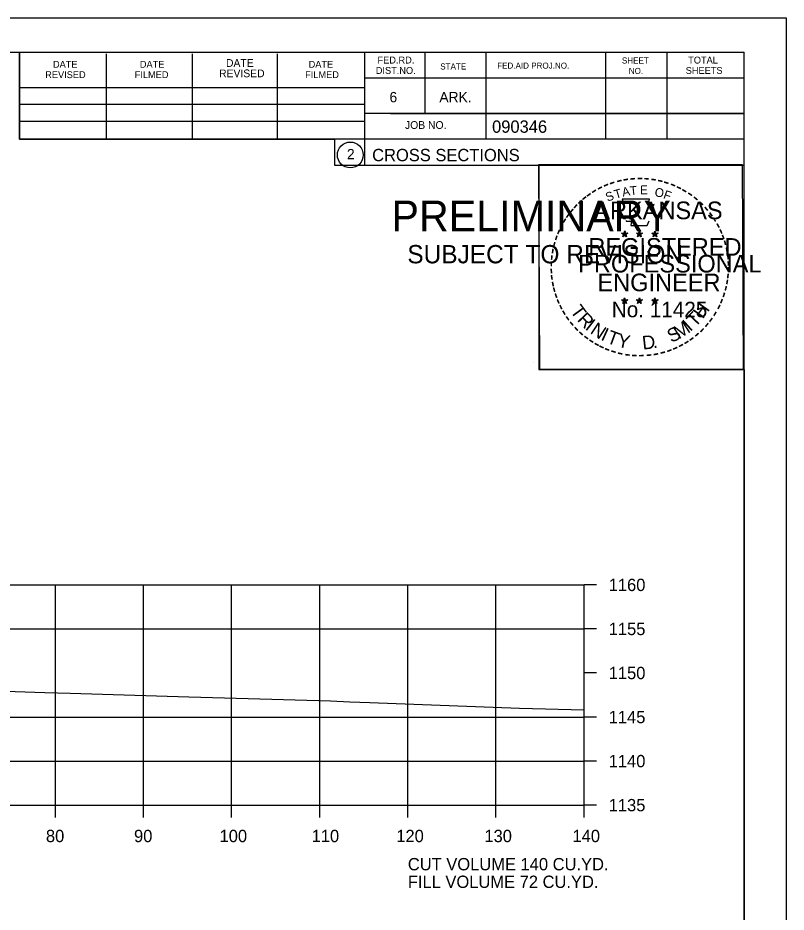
# Model space of a CAD drawing. Extents: x 1368971 to 1374497, y 378717 to 381839.
# Drawn here: x 1372484.6 to 1372571.8, y 381441.8 to 381543.3 of the extents above; entities that cross this region are included whole.
import ezdxf

# ---------------------------------------------------------------- set-up
doc = ezdxf.new("R2010")
doc.units = 0
for name, color, linetype in [('R_Axis', 7, 'Continuous'), ('R_Axis Annot', 7, 'Continuous'), ('R_Border', 7, 'Continuous'), ('R_Border PE', 7, 'Continuous'), ('R_Border Prem', 7, 'Continuous'), ('R_Exist Surface', 7, 'Continuous'), ('R_Grid', 7, 'Continuous'), ('R_No Plot', 7, 'Continuous')]:
    doc.layers.add(name, color=color, linetype=linetype)

msp = doc.modelspace()

# ---------------------------------------------------------------- linework, layer by layer
at = {"layer": 'R_Axis'}
for p, q in [((1372548.91, 381453.99), (1372548.91, 381478.99)), ((1372550.31, 381478.99), (1372548.91, 381478.99)), ((1372550.31, 381473.99), (1372548.91, 381473.99)), ((1372550.31, 381468.99), (1372548.91, 381468.99)), ((1372550.31, 381463.99), (1372548.91, 381463.99)), ((1372550.31, 381458.99), (1372548.91, 381458.99)), ((1372268.91, 381453.99), (1372548.91, 381453.99)), ((1372488.91, 381452.59), (1372488.91, 381453.99)), ((1372498.91, 381452.59), (1372498.91, 381453.99)), ((1372508.91, 381452.59), (1372508.91, 381453.99)), ((1372518.91, 381452.59), (1372518.91, 381453.99)), ((1372528.91, 381452.59), (1372528.91, 381453.99)), ((1372538.91, 381452.59), (1372538.91, 381453.99)), ((1372548.91, 381452.59), (1372548.91, 381453.99)), ((1372550.31, 381453.99), (1372548.91, 381453.99))]:
    msp.add_line(p, q, dxfattribs=at)
at = {"layer": 'R_Border'}
for p, q in [((1372250.91, 381539.45), (1372567.09, 381539.45)), ((1372484.83, 381529.57), (1372484.83, 381539.45)), ((1372494.69, 381529.57), (1372494.69, 381539.25)), ((1372504.45, 381529.57), (1372504.45, 381539.25)), ((1372514.13, 381529.57), (1372514.13, 381539.25)), ((1372523.99, 381539.45), (1372523.99, 381526.65)), ((1372530.83, 381539.45), (1372530.83, 381532.51)), ((1372537.77, 381539.45), (1372537.77, 381529.57)), ((1372551.35, 381539.45), (1372551.35, 381529.57)), ((1372558.29, 381539.45), (1372558.29, 381529.57)), ((1372567.09, 381333.99), (1372567.09, 381539.45)), ((1372567.09, 381536.51), (1372523.99, 381536.51)), ((1372567.09, 381536.53), (1372567.09, 381536.53)), ((1372484.83, 381535.43), (1372523.99, 381535.43)), ((1372484.83, 381533.57), (1372523.99, 381533.57)), ((1372567.09, 381532.51), (1372523.99, 381532.51)), ((1372526.95, 381532.51), (1372567.09, 381532.51)), ((1372484.83, 381529.57), (1372484.83, 381531.63)), ((1372484.83, 381531.63), (1372523.99, 381531.63)), ((1372567.09, 381529.57), (1372484.83, 381529.57)), ((1372523.99, 381526.65), (1372567.09, 381526.65))]:
    msp.add_line(p, q, dxfattribs=at)
msp.add_circle((1372522.38, 381527.79), 1.47, dxfattribs=at)
at = {"layer": 'R_Border PE'}
for p, q in [((1372553.18, 381518.91), (1372553.53, 381518.8)), ((1372553.18, 381518.91), (1372553.43, 381518.86)), ((1372553.18, 381518.91), (1372553.42, 381518.79)), ((1372553.31, 381518.5), (1372553.53, 381518.8)), ((1372553.53, 381519.16), (1372553.49, 381518.91)), ((1372553.53, 381518.8), (1372553.53, 381519.16)), ((1372553.53, 381519.16), (1372553.58, 381518.91)), ((1372553.88, 381518.91), (1372553.53, 381518.8)), ((1372553.74, 381518.5), (1372553.53, 381518.8)), ((1372553.88, 381518.91), (1372553.59, 381518.86)), ((1372553.74, 381518.5), (1372553.6, 381518.79)), ((1372553.88, 381518.91), (1372553.67, 381518.81)), ((1372554.85, 381518.91), (1372555.2, 381518.8)), ((1372554.85, 381518.91), (1372555.1, 381518.86)), ((1372554.85, 381518.91), (1372555.09, 381518.79)), ((1372554.98, 381518.5), (1372555.2, 381518.8)), ((1372555.2, 381519.16), (1372555.16, 381518.91)), ((1372555.2, 381518.8), (1372555.2, 381519.16)), ((1372555.2, 381519.16), (1372555.25, 381518.91)), ((1372555.55, 381518.91), (1372555.2, 381518.8)), ((1372555.41, 381518.5), (1372555.2, 381518.8)), ((1372555.55, 381518.91), (1372555.26, 381518.86)), ((1372555.41, 381518.5), (1372555.27, 381518.79)), ((1372555.55, 381518.91), (1372555.34, 381518.81)), ((1372556.61, 381518.9), (1372556.96, 381518.79)), ((1372556.61, 381518.9), (1372556.87, 381518.85)), ((1372556.61, 381518.9), (1372556.85, 381518.78)), ((1372556.75, 381518.49), (1372556.96, 381518.79)), ((1372556.96, 381519.15), (1372556.92, 381518.9)), ((1372556.96, 381518.79), (1372556.96, 381519.15)), ((1372556.96, 381519.15), (1372557.01, 381518.9)), ((1372557.31, 381518.9), (1372556.96, 381518.79)), ((1372557.18, 381518.49), (1372556.96, 381518.79)), ((1372557.31, 381518.9), (1372557.02, 381518.85)), ((1372557.18, 381518.49), (1372557.04, 381518.78)), ((1372557.31, 381518.9), (1372557.11, 381518.8)), ((1372553.31, 381518.5), (1372553.44, 381518.75)), ((1372553.31, 381518.5), (1372553.53, 381518.72)), ((1372553.74, 381518.5), (1372553.53, 381518.72)), ((1372554.98, 381518.5), (1372555.11, 381518.75)), ((1372554.98, 381518.5), (1372555.2, 381518.72)), ((1372555.41, 381518.5), (1372555.2, 381518.72)), ((1372556.75, 381518.49), (1372556.87, 381518.73)), ((1372556.75, 381518.49), (1372556.96, 381518.71)), ((1372557.18, 381518.49), (1372556.96, 381518.7)), ((1372553.18, 381511.34), (1372553.52, 381511.23)), ((1372553.18, 381511.34), (1372553.43, 381511.29)), ((1372553.18, 381511.34), (1372553.41, 381511.21)), ((1372553.31, 381510.93), (1372553.52, 381511.23)), ((1372553.31, 381510.93), (1372553.43, 381511.17)), ((1372553.31, 381510.93), (1372553.52, 381511.15)), ((1372553.52, 381511.59), (1372553.48, 381511.34)), ((1372553.52, 381511.23), (1372553.52, 381511.59)), ((1372553.52, 381511.59), (1372553.57, 381511.34)), ((1372553.87, 381511.34), (1372553.52, 381511.23)), ((1372553.74, 381510.93), (1372553.52, 381511.23)), ((1372553.74, 381510.93), (1372553.52, 381511.14)), ((1372553.87, 381511.34), (1372553.59, 381511.29)), ((1372553.74, 381510.93), (1372553.6, 381511.22)), ((1372553.87, 381511.34), (1372553.67, 381511.23)), ((1372554.84, 381511.34), (1372555.19, 381511.23)), ((1372554.84, 381511.34), (1372555.1, 381511.29)), ((1372554.84, 381511.34), (1372555.08, 381511.21)), ((1372554.98, 381510.93), (1372555.19, 381511.23)), ((1372554.98, 381510.93), (1372555.1, 381511.17)), ((1372554.98, 381510.93), (1372555.19, 381511.15)), ((1372555.19, 381511.59), (1372555.15, 381511.34)), ((1372555.19, 381511.23), (1372555.19, 381511.59)), ((1372555.19, 381511.59), (1372555.24, 381511.34)), ((1372555.54, 381511.34), (1372555.19, 381511.23)), ((1372555.41, 381510.93), (1372555.19, 381511.23)), ((1372555.41, 381510.93), (1372555.19, 381511.14)), ((1372555.54, 381511.34), (1372555.25, 381511.29)), ((1372555.41, 381510.93), (1372555.27, 381511.22)), ((1372555.54, 381511.34), (1372555.34, 381511.23)), ((1372556.61, 381511.33), (1372556.96, 381511.22)), ((1372556.61, 381511.33), (1372556.86, 381511.28)), ((1372556.61, 381511.33), (1372556.85, 381511.2)), ((1372556.74, 381510.92), (1372556.96, 381511.22)), ((1372556.74, 381510.92), (1372556.87, 381511.16)), ((1372556.74, 381510.92), (1372556.96, 381511.14)), ((1372556.96, 381511.58), (1372556.92, 381511.33)), ((1372556.96, 381511.22), (1372556.96, 381511.58)), ((1372556.96, 381511.58), (1372557.01, 381511.33)), ((1372557.31, 381511.33), (1372556.96, 381511.22)), ((1372557.17, 381510.92), (1372556.96, 381511.22)), ((1372557.17, 381510.92), (1372556.96, 381511.13)), ((1372557.31, 381511.33), (1372557.02, 381511.28)), ((1372557.17, 381510.92), (1372557.04, 381511.21)), ((1372557.31, 381511.33), (1372557.1, 381511.22))]:
    msp.add_line(p, q, dxfattribs=at)
for points in [[(1372553.22, 381522.79), (1372553.49, 381521.96)], [(1372556.73, 381521.87), (1372556.87, 381522.15), (1372556.19, 381522.13), (1372556.34, 381522.79), (1372553.22, 381522.79)], [(1372553.71, 381520.36), (1372553.71, 381520.28), (1372554.28, 381520.26), (1372554.22, 381519.79), (1372556.09, 381519.79), (1372556.29, 381520.32)], [(1372553.53, 381519.16), (1372553.74, 381518.5), (1372553.18, 381518.91), (1372553.88, 381518.91), (1372553.31, 381518.5), (1372553.53, 381519.16)], [(1372555.2, 381519.16), (1372555.41, 381518.5), (1372554.85, 381518.91), (1372555.55, 381518.91), (1372554.98, 381518.5), (1372555.2, 381519.16)], [(1372556.96, 381519.15), (1372557.18, 381518.49), (1372556.61, 381518.9), (1372557.31, 381518.9), (1372556.75, 381518.49), (1372556.96, 381519.15)], [(1372553.52, 381511.59), (1372553.74, 381510.93), (1372553.18, 381511.34), (1372553.87, 381511.34), (1372553.31, 381510.93), (1372553.52, 381511.59)], [(1372555.19, 381511.59), (1372555.41, 381510.93), (1372554.84, 381511.34), (1372555.54, 381511.34), (1372554.98, 381510.93), (1372555.19, 381511.59)], [(1372556.96, 381511.58), (1372557.17, 381510.92), (1372556.61, 381511.33), (1372557.31, 381511.33), (1372556.74, 381510.92), (1372556.96, 381511.58)]]:
    msp.add_lwpolyline(points, dxfattribs=at)
for centre, radius in [((1372553.53, 381518.8), 0.172), ((1372553.53, 381518.8), 0.145), ((1372553.53, 381518.8), 0.116), ((1372553.53, 381518.8), 0.0991), ((1372553.53, 381518.8), 0.0747), ((1372553.53, 381518.8), 0.0495), ((1372553.53, 381518.8), 0.0296), ((1372555.2, 381518.8), 0.172), ((1372555.2, 381518.8), 0.145), ((1372555.2, 381518.8), 0.116), ((1372555.2, 381518.8), 0.0991), ((1372555.2, 381518.8), 0.0747), ((1372555.2, 381518.8), 0.0495), ((1372555.2, 381518.8), 0.0296), ((1372556.96, 381518.79), 0.172), ((1372556.96, 381518.79), 0.145), ((1372556.96, 381518.79), 0.116), ((1372556.96, 381518.79), 0.0991), ((1372556.96, 381518.79), 0.0747), ((1372556.96, 381518.79), 0.0495), ((1372556.96, 381518.79), 0.0296), ((1372553.52, 381511.22), 0.172), ((1372553.52, 381511.22), 0.145), ((1372553.52, 381511.22), 0.116), ((1372553.52, 381511.22), 0.0991), ((1372553.52, 381511.22), 0.0747), ((1372553.52, 381511.22), 0.0495), ((1372553.52, 381511.22), 0.0296), ((1372555.19, 381511.22), 0.172), ((1372555.19, 381511.22), 0.145), ((1372555.19, 381511.22), 0.116), ((1372555.19, 381511.22), 0.0991), ((1372555.19, 381511.22), 0.0747), ((1372555.19, 381511.22), 0.0495), ((1372555.19, 381511.22), 0.0296), ((1372556.96, 381511.21), 0.172), ((1372556.96, 381511.21), 0.145), ((1372556.96, 381511.21), 0.116), ((1372556.96, 381511.21), 0.0991), ((1372556.96, 381511.21), 0.0747), ((1372556.96, 381511.21), 0.0495), ((1372556.96, 381511.21), 0.0296)]:
    msp.add_circle(centre, radius, dxfattribs=at)
at = {"layer": 'R_Exist Surface'}
msp.add_lwpolyline([(1372475.29, 381467.2), (1372487.72, 381466.78), (1372490.6, 381466.69), (1372504.05, 381466.29), (1372510.77, 381466.09), (1372520.15, 381465.82), (1372522.34, 381465.72), (1372524.61, 381465.64), (1372541.58, 381465.01), (1372548.91, 381464.79)], dxfattribs=at)
at = {"layer": 'R_Grid'}
for p, q in [((1372268.91, 381478.99), (1372548.91, 381478.99)), ((1372488.91, 381453.99), (1372488.91, 381478.99)), ((1372498.91, 381453.99), (1372498.91, 381478.99)), ((1372508.91, 381453.99), (1372508.91, 381478.99)), ((1372518.91, 381453.99), (1372518.91, 381478.99)), ((1372528.91, 381453.99), (1372528.91, 381478.99)), ((1372538.91, 381453.99), (1372538.91, 381478.99)), ((1372548.91, 381453.99), (1372548.91, 381478.99)), ((1372268.91, 381473.99), (1372548.91, 381473.99)), ((1372268.91, 381463.99), (1372548.91, 381463.99)), ((1372268.91, 381458.99), (1372548.91, 381458.99)), ((1372268.91, 381453.99), (1372548.91, 381453.99))]:
    msp.add_line(p, q, dxfattribs=at)
at = {"layer": 'R_No Plot'}
for p, q in [((1372238.51, 381543.35), (1372571.85, 381543.35)), ((1372543.13, 381504.2), (1372543.13, 381504.2))]:
    msp.add_line(p, q, dxfattribs=at)
for points in [[(1372238.51, 381543.35), (1372571.85, 381543.35), (1372571.85, 381330.01), (1372238.51, 381330.01)], [(1372484.83, 381539.45), (1372484.83, 381529.57), (1372520.57, 381529.57), (1372520.57, 381526.65), (1372543.77, 381526.65), (1372543.77, 381503.44), (1372567.09, 381503.44), (1372567.09, 381333.99), (1372250.91, 381333.99), (1372250.91, 381539.45)], [(1372543.77, 381526.69), (1372566.86, 381526.69), (1372566.98, 381503.44), (1372543.88, 381503.44)]]:
    msp.add_lwpolyline(points, close=True, dxfattribs=at)

# ---------------------------------------------------------------- texts
at = {"layer": 'R_Axis Annot'}
for s, p in [('1160', (1372551.71, 381478.29)), ('1155', (1372551.71, 381473.29)), ('1150', (1372551.71, 381468.29)), ('1145', (1372551.71, 381463.29)), ('1140', (1372551.71, 381458.29)), ('1135', (1372551.71, 381453.29)), ('80', (1372487.83, 381449.79)), ('90', (1372497.83, 381449.79)), ('100', (1372507.54, 381449.79)), ('110', (1372517.99, 381449.79)), ('120', (1372527.6, 381449.79)), ('130', (1372537.6, 381449.79)), ('140', (1372547.6, 381449.79)), ('CUT VOLUME 140 CU.YD.', (1372528.91, 381446.59)), ('FILL VOLUME 72 CU.YD.', (1372528.91, 381444.59))]:
    msp.add_text(s, height=1.4, dxfattribs=at).set_placement(p)
at = {"layer": 'R_Border'}
for s, height, p in [('DATE', 0.782, (1372488.63, 381537.69)), ('DATE', 0.782, (1372498.49, 381537.69)), ('DATE', 0.879, (1372508.27, 381537.79)), ('DATE', 0.782, (1372517.65, 381537.69)), ('FED.RD.', 0.782, (1372525.47, 381538.17)), ('STATE', 0.684, (1372532.59, 381537.49)), ('FED.AID PROJ.NO.', 0.684, (1372539.05, 381537.59)), ('SHEET', 0.684, (1372553.21, 381538.17)), ('TOTAL', 0.782, (1372560.73, 381538.17)), ('REVISED', 0.782, (1372487.75, 381536.51)), ('FILMED', 0.782, (1372497.91, 381536.51)), ('REVISED', 0.879, (1372507.49, 381536.61)), ('FILMED', 0.782, (1372517.25, 381536.51)), ('DIST.NO.', 0.782, (1372525.27, 381536.99)), ('NO.', 0.684, (1372553.99, 381536.99)), ('SHEETS', 0.782, (1372560.45, 381536.99)), ('6', 1.17, (1372526.83, 381533.77)), ('ARK.', 1.172, (1372532.49, 381533.77)), ('JOB NO.', 0.879, (1372528.59, 381530.75)), ('2', 1.17, (1372522, 381527.3)), ('CROSS SECTIONS', 1.4, (1372524.86, 381527.08))]:
    msp.add_text(s, height=height, dxfattribs=at).set_placement(p)
msp.add_text('090346', height=1.4, rotation=360, dxfattribs=at).set_placement((1372538.47, 381530.31))
at = {"layer": 'R_Border PE'}
for s, height, rotation, p in [('-', 1.6, 13.6301, (1372552.72, 381524.16)), ('-', 1.6, 10.2193, (1372553.4, 381524.32)), ('-', 1.6, 5.8968, (1372554.13, 381524.43)), ('-', 1.6, 0.1862, (1372554.9, 381524.5)), ('-', 1.6, 357.743, (1372555.62, 381524.49)), ('-', 1.6, 352.1617, (1372556.36, 381524.43)), ('-', 1.6, 347.2049, (1372557.08, 381524.32)), ('-', 1.6, 34.0636, (1372550.1, 381522.96)), ('-', 1.6, 28.7918, (1372550.7, 381523.33)), ('-', 1.6, 24.3072, (1372551.33, 381523.65)), ('-', 1.6, 19.1761, (1372551.97, 381523.91)), ('T', 1, 16.4036, (1372552.49, 381522.8)), ('A', 1, 11.2132, (1372553.32, 381523.05)), ('T', 1, 6.0228, (1372554.16, 381523.21)), ('E', 1, 0.8323, (1372555.27, 381523.32)), ('O', 1, 350.4515, (1372556.87, 381523.11)), ('-', 1.6, 342.3362, (1372557.72, 381524.16)), ('-', 1.6, 337.8551, (1372558.45, 381523.94)), ('-', 1.6, 334.1211, (1372559.08, 381523.67)), ('-', 1.6, 329.6409, (1372559.66, 381523.38)), ('-', 1.6, 38.9507, (1372549.05, 381522.19)), ('-', 1.6, 36.2317, (1372549.53, 381522.56)), ('S', 1, 21.594, (1372551.58, 381522.47)), ('F', 1, 340.0707, (1372557.83, 381522.89)), ('-', 1.6, 325.8627, (1372560.31, 381523.02)), ('-', 1.6, 320.5297, (1372560.92, 381522.6)), ('-', 1.6, 48.423, (1372548.17, 381521.29)), ('-', 1.6, 42.9622, (1372548.62, 381521.77)), ('-', 1.6, 315.5786, (1372561.52, 381522.11)), ('-', 1.6, 309.8797, (1372562.08, 381521.56)), ('-', 1.6, 54.2325, (1372547.35, 381520.24)), ('-', 1.6, 50.6142, (1372547.77, 381520.8)), ('-', 1.6, 306.6522, (1372562.61, 381520.96)), ('-', 1.6, 62.8713, (1372546.72, 381519.1)), ('-', 1.6, 58.0706, (1372547.03, 381519.71)), ('-', 1.4, 303.6753, (1372563.1, 381520.39)), ('-', 1.6, 299.6684, (1372563.41, 381519.78)), ('-', 1.6, 67.7743, (1372546.46, 381518.49)), ('-', 1.6, 294.6628, (1372563.74, 381519.17)), ('-', 1.6, 290.5728, (1372564, 381518.59)), ('-', 1.6, 75.461, (1372546.04, 381517.14)), ('-', 1.6, 72.3945, (1372546.24, 381517.86)), ('-', 1.6, 285.1233, (1372564.23, 381518.01)), ('-', 1.6, 81.2013, (1372545.91, 381516.43)), ('-', 1.6, 280.5493, (1372564.43, 381517.27)), ('-', 1.6, 85.1863, (1372545.83, 381515.74)), ('-', 1.6, 276.5962, (1372564.59, 381516.5)), ('-', 1.6, 274.3301, (1372564.65, 381515.78)), ('-', 1.6, 94.1959, (1372545.84, 381514.31)), ('-', 1.6, 89.0622, (1372545.81, 381515.04)), ('-', 1.6, 269.9407, (1372564.69, 381515.15)), ('-', 1.6, 98.9479, (1372545.91, 381513.64)), ('-', 1.6, 263.5172, (1372564.67, 381514.48)), ('-', 1.6, 101.7149, (1372546.05, 381512.91)), ('-', 1.6, 105.4578, (1372546.21, 381512.32)), ('-', 1.6, 255.7626, (1372564.49, 381513.15)), ('-', 1.6, 260.9953, (1372564.6, 381513.83)), ('-', 1.6, 109.0874, (1372546.43, 381511.69)), ('-', 1.6, 252.8681, (1372564.3, 381512.43)), ('-', 1.6, 114.0643, (1372546.68, 381511.09)), ('-', 1.6, 115.7288, (1372546.99, 381510.47)), ('T', 1.54, 306.0406, (1372547.28, 381510.06)), ('H', 1.54, 54.6088, (1372562.4, 381509.1)), ('-', 1.6, 244.6197, (1372563.82, 381511.13)), ('-', 1.6, 247.8887, (1372564.08, 381511.76)), ('-', 1.6, 120.4471, (1372547.34, 381509.89)), ('R', 1.54, 314.005, (1372548.05, 381509.02)), ('T', 1.54, 46.6444, (1372561.51, 381508.16)), ('-', 1.6, 239.0712, (1372563.43, 381510.38)), ('-', 1.6, 125.8934, (1372547.75, 381509.32)), ('-', 1.6, 130.7181, (1372548.21, 381508.77)), ('I', 1.54, 321.9694, (1372548.95, 381508.08)), ('N', 1.54, 326.5002, (1372549.51, 381507.61)), ('M', 1.54, 32.6563, (1372559.67, 381506.83)), ('I', 1.54, 42.1136, (1372560.95, 381507.68)), ('-', 1.6, 231.2538, (1372562.59, 381509.16)), ('-', 1.6, 233.8452, (1372563.02, 381509.72)), ('-', 1.6, 134.2238, (1372548.72, 381508.23)), ('-', 1.6, 138.9338, (1372549.25, 381507.76)), ('I', 1.54, 335.3603, (1372550.72, 381506.83)), ('T', 1.54, 339.8912, (1372551.38, 381506.5)), ('S', 1.54, 26.9312, (1372558.83, 381506.43)), ('-', 1.6, 221.0851, (1372561.59, 381508.09)), ('-', 1.6, 225.7653, (1372562.11, 381508.59)), ('-', 1.6, 144.6463, (1372549.81, 381507.36)), ('-', 1.6, 148.0898, (1372550.37, 381506.99)), ('Y', 1.54, 347.8556, (1372552.6, 381506.05)), ('D', 1.54, 6.3969, (1372555.59, 381505.69)), ('-', 1.6, 212.2491, (1372560.51, 381507.23)), ('-', 1.6, 215.7363, (1372561.04, 381507.61)), ('-', 1.6, 151.5704, (1372550.95, 381506.66)), ('-', 1.6, 154.6002, (1372551.47, 381506.41)), ('-', 1.6, 158.5612, (1372552.09, 381506.16)), ('-', 1.6, 162.7983, (1372552.78, 381505.95)), ('.', 1.54, 13.7642, (1372556.78, 381505.82)), ('-', 1.6, 200.7184, (1372558.71, 381506.29)), ('-', 1.6, 204.2516, (1372559.33, 381506.56)), ('-', 1.6, 207.3568, (1372559.95, 381506.88)), ('-', 1.6, 167.5555, (1372553.49, 381505.78)), ('-', 1.6, 173.1155, (1372554.27, 381505.67)), ('-', 1.6, 176.5183, (1372555.01, 381505.62)), ('-', 1.6, 181.5918, (1372555.76, 381505.64)), ('-', 1.6, 185.8167, (1372556.57, 381505.72)), ('-', 1.6, 191.2858, (1372557.3, 381505.85)), ('-', 1.6, 195.4743, (1372558.03, 381506.05))]:
    msp.add_text(s, height=height, rotation=rotation, dxfattribs=at).set_placement(p)
for s, height, p in [('ARKANSAS', 2, (1372550.07, 381520.5)), ('DWB', 0.01, (1372553.52, 381518.79)), ('DWB', 0.01, (1372555.19, 381518.79)), ('DWB', 0.01, (1372556.95, 381518.78)), ('REGISTERED', 2, (1372549.4, 381516.35)), ('PROFESSIONAL', 2, (1372548.25, 381514.45)), ('ENGINEER', 2, (1372550.43, 381512.32)), ('No. 11425', 1.757, (1372552.06, 381509.37)), ('DWB', 0.01, (1372553.51, 381511.22)), ('DWB', 0.01, (1372555.18, 381511.22)), ('DWB', 0.01, (1372556.95, 381511.21))]:
    msp.add_text(s, height=height, dxfattribs=at).set_placement(p)
at = {"layer": 'R_Border Prem'}
for s, height, p in [('PRELIMINARY', 3.5, (1372527.05, 381519.12)), ('DWB', 0.01, (1372527.79, 381520.97)), ('SUBJECT TO REVISION', 2.0751, (1372528.85, 381515.49))]:
    msp.add_text(s, height=height, dxfattribs=at).set_placement(p)

doc.saveas('drawing.dxf')
